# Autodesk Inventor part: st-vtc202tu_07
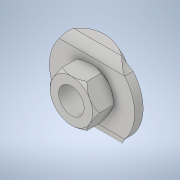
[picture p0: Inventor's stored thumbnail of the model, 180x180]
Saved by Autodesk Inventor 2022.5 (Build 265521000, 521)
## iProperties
Created: 2021-08
Part Number: st-vtc202tu_07
Material: 一般
Document SubType Name: Modeling
Designer: ImaoCorp
Density: 1 g/cm^3
Appearance: 既定
Author: ImaoCorp
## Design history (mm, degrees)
feature "st-vtc202tu_07"
node "ソリッド1"
